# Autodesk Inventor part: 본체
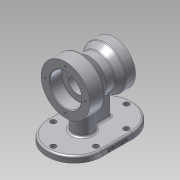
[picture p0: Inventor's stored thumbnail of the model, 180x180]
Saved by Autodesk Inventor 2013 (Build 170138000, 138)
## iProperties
Created: 2020-01
Part Number: 본체
Material: 알루미늄 6061
Document SubType Name: Modeling
Designer: Administrator
Density: 2.71 g/cm^3
Mass: 939.613 g
Surface Area: 655.36 cm^2
Volume: 346.721 cm^3
Author: Administrator
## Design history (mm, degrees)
sketch "스케치1"
  geometry: L1 (-40, 0)-(40, 0); L2 (-40, 0)-(-40, 26); L3 (-40, 40)-(-16, 40); L4 (-16, 40)-(-1.103, 27.5); L5 (-1.103, 27.5)-(13.289, 27.5); L6 (13.289, 27.5)-(24, 35); L7 (24, 35)-(40, 35); L8 (40, 35)-(40, 20); L9 (-40, 26)-(-20, 26); L10 (-20, 26)-(-20, 16); L11 (-20, 16)-(23, 16); L12 (23, 16)-(23, 20); L13 (23, 20)-(40, 20); L14 (-40, 26)-(-40, 40); L15 (40, 20)-(40, 0); 1 further point
  constraints: 30 end point, 9 perpendicular, 8 parallel, 1 horizontal, 1 midpoint
  dimensions: "d0" = 80 distance of L1.start L1.end; "d2" = 24 distance of L3.start L3.end; "d4" = 40 deg angle of L5 L4; "d5" = 35 deg angle of L5 L6; "d6" = 20 distance of L2.end L9.end; "d7" = 17 distance of L12.end L8.end; "d8" = 80 diameter of L3 L1; "d9" = 55 diameter of L5 L1; "d10" = 52 diameter of L9 L1; "d11" = 40 diameter of L13 L1; "d12" = 32 diameter of L11 L1; "d13" = 16 distance from line of L6.end L8; "d14" = 70 diameter of L7 L1; "d15" = 40 distance from line of point (0, 0) L2
revolve "회전1" sketch "스케치1" stored, may be unused: angle "d16" = 90 deg
sketch "스케치2"
  geometry: 1 further point
node "작업 평면1"
sketch "스케치3"
  geometry: L1 (25, 45)-(-25, 45); L2 (25, -45)-(-25, -45); A1 r 45 centre (25, 0) between (25, 45) and (25, -45); A2 r 45 centre (-25, 0) between (-25, 45) and (-25, -45); 2 further points
  constraints: 4 end point, 4 point on circle, 4 tangent, 2 centre point, 2 horizontal alignment, 1 equal radius, 1 midpoint, 1 vertical alignment
  dimensions: "d18" = 45 radius of A1; "d20" = 50 distance of A2.centre A1.centre
extrude "돌출1" join sketch "스케치3" distance "d21" = 10; taper "d22" = 0 deg
sketch "스케치6"
  geometry: L1 (-12, 5)-(30, 5); L2 (30, 5)-(30, -5); L3 (30, -5)-(-12, -5); L4 (-12, -5)-(-12, 5); L5 (40, -35)-(40, 35) reference; C1 r 16 at (-12, 0); A1 r 45 centre (-25, 0) between (-25, 45) and (-25, -45) reference; 2 further points
  constraints: 8 end point, 2 coincident, 2 parallel, 1 centre point, 1 horizontal, 1 horizontal alignment, 1 midpoint, 1 perpendicular
  dimensions: "d30" = 16 radius of C1; "d31" = 10 distance of L1.end L2.end; "d78" = 10 distance between parallel lines of L2 L5; "d79" = 58 dimension on A1 L4
extrude "돌출2" join sketch "스케치6" stored distance "d33" = 10; taper "d34" = 0 deg
sketch "스케치7"
  geometry: L1 (25, 45)-(-25, 45) reference; L2 (-25, -45)-(25, -45) reference; L3 (25, -35)-(-25, -35); L4 (-25, 35)-(25, 35); C1 r 4.5 at (-60, 0); A1 r 45 centre (25, 0) between (25, -45) and (25, 45) reference; A2 r 45 centre (-25, 0) between (-25, 45) and (-25, -45) reference; A3 r 35 centre (25, 0) between (25, -35) and (25, 35); A4 r 35 centre (-25, 0) between (-25, 35) and (-25, -35); 1 further point
  constraints: 5 point on circle, 4 end point, 3 centre point, 3 other
  dimensions: "d35" = 10 distance between parallel lines of L4 L1; "d36" = 9 diameter of C1
extrude "돌출3" cut sketch "스케치7" stored distance "d37" = 10; taper "d38" = 0 deg
sketch "스케치9"
  geometry: L1 (25, 45)-(-25, 45) reference; L2 (-25, -45)-(25, -45) reference; L3 (-25, 35)-(25, 35); L4 (25, -35)-(-25, -35); C1 r 4.5 at (-25, 35); C2 r 4.5 at (25, 35); C3 r 4.5 at (60, 0); C4 r 4.5 at (25, -35); C5 r 4.5 at (-25, -35); A1 r 45 centre (25, 0) between (25, -45) and (25, 45) reference; A2 r 45 centre (-25, 0) between (-25, 45) and (-25, -45) reference; A3 r 35 centre (25, 0) between (25, -35) and (25, 35); A4 r 35 centre (-25, 0) between (-25, 35) and (-25, -35); 1 further point
  constraints: 7 centre point, 5 point on circle, 4 coincident, 4 end point, 4 equal radius, 3 other
  dimensions: "d39" = 10 distance between parallel lines of L3 L1; "d40" = 9 diameter of C1
extrude "돌출4" cut sketch "스케치9" stored distance "d41" = 10; taper "d42" = 0 deg
sketch "스케치12"
  geometry: C1 r 20 at (0, 0) reference; 1 further point
  constraints: 1 vertical alignment
  dimensions: "d45" = 27.5 distance of C1.centre point (0, 27.5)
hole "구멍1" sketch "스케치12" at (0, 27.5) diameter "d46" = 3.242; stored, may be unused: countersink angle "d50" = 82 deg, drill point angle "d52" = 118 deg; dims "d47" = 9, "d48" = 3.023, "d49" = 2, "d51" = 11
sketch "스케치13"
  geometry: C1 r 40 at (0, 0) reference; 1 further point
  constraints: 1 vertical alignment
  dimensions: "d56" = 33 distance of C1.centre point (0, 33)
hole "구멍2" sketch "스케치13" at (0, 33) diameter "d57" = 3.242; stored, may be unused: countersink angle "d61" = 82 deg, drill point angle "d63" = 118 deg; dims "d58" = 9, "d59" = 3.023, "d60" = 2, "d62" = 11
fillet "모깎기1" dims "d67" = 0.3
chamfer "모따기1" distance "d68" = 1; stored, may be unused: second distance "d69" = 2, angle "d70" = 45 deg
fillet "모깎기2" dims "d71" = 3
fillet "모깎기3" dims "d72" = 3
fillet "모깎기4" dims "d73" = 3
sketch "스케치14"
  geometry: L1 (0, 0)-(50, 0) reference; L2 (-45, 0)-(-45, 7) reference; 2 further points
  constraints: 1 other
  dimensions: "d74" = 70 distance from line of L2 point (25, 4); "d75" = 4 distance from line of L1 point (25, 4)
feature "엠보싱1" sketch "스케치14" dims "d0" = 80, "d2" = 24, "d4" = 40 deg, "d5" = 35 deg, "d6" = 20, "d7" = 17, "d8" = 80, "d9" = 55, "d10" = 52, "d11" = 40, "d12" = 32, "d13" = 16, "d14" = 70, "d15" = 40, "d18" = 45, "d20" = 50, "d76" = 0.5, "d77" = 0
node "솔리드1"
pattern_circular "원형 패턴1" dims angle "d54" = 360 deg
pattern_circular "원형 패턴2" dims angle "d65" = 360 deg
